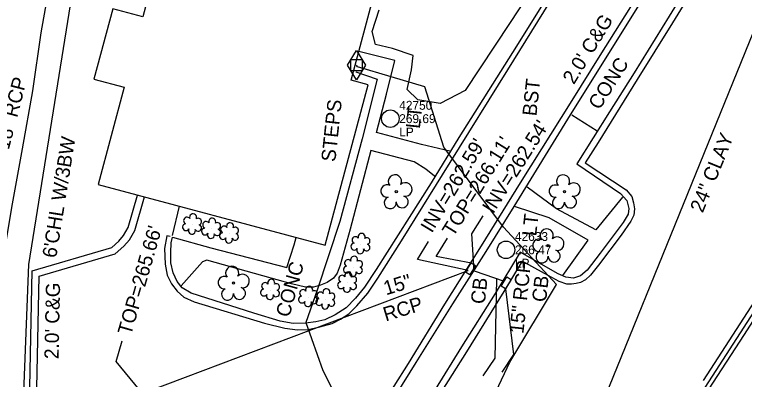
# Model space of a CAD drawing. Extents: x 2100323 to 2109811, y 740376 to 749755.
# Drawn here: x 2105531.2 to 2105736.4, y 742326 to 742428.5 of the extents above; entities that cross this region are included whole.
import ezdxf

# ---------------------------------------------------------------- set-up
doc = ezdxf.new("R2010")
doc.units = 0
for name, color, linetype in [('Exist Building', 7, 'Continuous'), ('Exist Other Culture Area Outline', 7, 'Continuous'), ('Exist Other Culture Area Outline Text', 7, 'Continuous'), ('Exist Other Culture Fence Line', 7, 'Continuous'), ('Exist Other Culture Fence Line Text', 7, 'Continuous'), ('Exist Roads Curbs', 7, 'Continuous'), ('Exist Roads Curbs Text', 7, 'Continuous'), ('Exist Roads EOP Other', 7, 'Continuous'), ('Exist Roads EOP Other Text', 7, 'Continuous'), ('Exist Structure Minor Catch Basin', 7, 'Continuous'), ('Exist Structure Minor Catch Basin Text', 7, 'Continuous'), ('Exist Structure Minor Catch Basin Top Elevation', 7, 'Continuous'), ('Exist Structure Minor Drop Inlet Top Elevation', 7, 'Continuous'), ('Exist Structure Minor Pipes RCP 15 Inch', 7, 'Continuous'), ('Exist Structure Minor Pipes RCP 15 Inch Invert', 7, 'Continuous'), ('Exist Structure Minor Pipes RCP 15 Inch Leader', 7, 'Continuous'), ('Exist Structure Minor Pipes RCP 15 Inch Text', 7, 'Continuous'), ('Exist Structure Minor Pipes RCP 18 Inch Invert', 7, 'Continuous'), ('Exist Utilities Gas Meter CELL', 7, 'Continuous'), ('Exist Utilities Gas UG Line SUE LOS B', 7, 'Continuous'), ('Exist Utilities Other Pole CELL', 7, 'Continuous'), ('Exist Utilities Other Pole Cogo Comment', 7, 'Continuous'), ('Exist Utilities Other Pole Cogo Elevation', 7, 'Continuous'), ('Exist Utilities Other Pole Cogo Number', 7, 'Continuous'), ('Exist Utilities Other Pole Text', 7, 'Continuous'), ('Exist Utilities Power UG Cable SUE LOS B', 7, 'Continuous'), ('Exist Utilities Sanitary Sewer UG Line', 7, 'Continuous'), ('Exist Utilities Sanitary Sewer UG Line Text', 7, 'Continuous'), ('Exist Vegetation Shrub CELL', 7, 'Continuous'), ('Exist Vegetation Tree CELL', 7, 'Continuous'), ('Exist Vegetation Woods Line', 7, 'Continuous')]:
    doc.layers.add(name, color=color, linetype=linetype)

msp = doc.modelspace()

# ---------------------------------------------------------------- linework, layer by layer
at = {"layer": 'Exist Building'}
msp.add_lwpolyline([(2105596.14, 742536.08), (2105567.25, 742427.88), (2105558.83, 742430.13), (2105553.55, 742410.38), (2105562.04, 742408.11), (2105554.73, 742380.72), (2105618.6, 742363.67), (2105630.65, 742408.77), (2105625.88, 742410.05), (2105632.74, 742435.75), (2105644.12, 742432.72), (2105651.94, 742461.99), (2105640.03, 742465.17), (2105654.78, 742520.42)], close=True, dxfattribs=at)
for points in [[(2105670.98, 742240.15), (2105682.89, 742258.66), (2105692.8, 742273.74), (2105709.7, 742299.48), (2105723.54, 742320.83), (2105738.21, 742343.59), (2105757.16, 742372.53), (2105770.97, 742393.51), (2105781.47, 742409.84), (2105802.03, 742441.27), (2105818.56, 742466.6)], [(2105575.65, 742366.38), (2105577.59, 742374.62)]]:
    msp.add_lwpolyline(points, dxfattribs=at)
at = {"layer": 'Exist Other Culture Area Outline'}
for points in [[(2105653.58, 742390.07), (2105645.68, 742391.97), (2105633.01, 742395.33), (2105635.8, 742406.1), (2105638.1, 742415.58), (2105628.05, 742418.17)], [(2105695, 742395.73), (2105687.91, 742400.26)], [(2105649.32, 742383.1), (2105646.89, 742385.09), (2105643.56, 742387.13), (2105631.38, 742390.32), (2105625.57, 742368.2), (2105622.81, 742358.04), (2105621.96, 742355.8), (2105620.94, 742354.4), (2105619.12, 742353.17), (2105617.25, 742352.42), (2105615.32, 742351.93), (2105612.98, 742351.89), (2105609.12, 742352.82), (2105600.99, 742355.1), (2105585.27, 742359.5), (2105584.08, 742359.04), (2105578.1, 742352.28)], [(2105702.12, 742377.16), (2105694.64, 742367.97), (2105683.57, 742373.95), (2105675.31, 742379.99)], [(2105685.36, 742355.15), (2105692.46, 742365.1), (2105681.58, 742371.38), (2105671.8, 742374.52)], [(2105575.64, 742365.95), (2105586.38, 742362.98), (2105607.78, 742357.43), (2105609.87, 742363.75), (2105610.36, 742365.87)]]:
    msp.add_lwpolyline(points, dxfattribs=at)
at = {"layer": 'Exist Other Culture Fence Line'}
for points in [[(2105532.84, 742296.01), (2105535.28, 742358.25), (2105552.31, 742464.54)], [(2105598.74, 742236.53), (2105628.53, 742225.99), (2105656.39, 742215.68), (2105671.05, 742239.06), (2105693.86, 742273.76), (2105715.01, 742305.6), (2105736.43, 742338.64), (2105757.27, 742371), (2105783.06, 742409.27), (2105785.25, 742412.99), (2105810.8, 742452.1), (2105819.72, 742465.67)]]:
    msp.add_lwpolyline(points, dxfattribs=at)
at = {"layer": 'Exist Roads Curbs'}
for points in [[(2105690.33, 742448.48), (2105671.22, 742417.88), (2105656.15, 742393.95), (2105648.36, 742381.17), (2105632.9, 742356.84), (2105629.65, 742351.91), (2105627.09, 742348.77), (2105624.42, 742346.09), (2105621.36, 742344.13), (2105618.47, 742342.74), (2105615.94, 742342.14), (2105612.99, 742341.76), (2105609.57, 742341.66), (2105605.93, 742342.36), (2105598.49, 742344.58), (2105580.85, 742350.19), (2105578.34, 742351.75), (2105576.98, 742353.5), (2105575.81, 742355.91), (2105575.19, 742358.71), (2105575.18, 742361.62), (2105575.28, 742364.34), (2105575.64, 742365.95)], [(2105725.62, 742444.93), (2105715.29, 742428.05), (2105705.47, 742412.16), (2105698.53, 742401.2), (2105689.34, 742386.6), (2105701.64, 742378.23), (2105703.35, 742376.24), (2105703.98, 742373.97), (2105703.77, 742372.45), (2105702.38, 742370.1), (2105695.89, 742361.46), (2105692.2, 742356.71), (2105690.33, 742355.05), (2105688.34, 742354.41), (2105686.26, 742354.72), (2105684.05, 742355.65), (2105673.41, 742361.75), (2105666.4, 742350.11), (2105656.91, 742335.11), (2105649.49, 742323.1)], [(2105631.35, 742310.24), (2105644.11, 742330.75), (2105654.42, 742347.24), (2105663.84, 742361.96), (2105671.7, 742374.58), (2105687.56, 742400.31), (2105696.19, 742414.13), (2105707.73, 742432.51)], [(2105535.38, 742319.12), (2105536.16, 742356.48), (2105558.53, 742363.03), (2105560.54, 742364.83), (2105561.86, 742366.4), (2105563.19, 742368.62), (2105565.81, 742377.76)]]:
    msp.add_lwpolyline(points, dxfattribs=at)
at = {"layer": 'Exist Roads EOP Other'}
for points in [[(2105574.95, 742366.16), (2105574, 742366.32), (2105573.39, 742362.75), (2105573.6, 742358.39), (2105574.17, 742355.24), (2105575.35, 742352.81), (2105576.95, 742350.79), (2105578.79, 742349.12), (2105581.72, 742347.78), (2105601.53, 742341.78), (2105607.17, 742340.41), (2105610.81, 742339.89), (2105613.82, 742340.03), (2105617.09, 742340.71), (2105620.54, 742341.69), (2105622.87, 742342.91), (2105625.22, 742344.38), (2105627.44, 742346.64), (2105630.52, 742350.18), (2105633.33, 742354.4), (2105640.04, 742364.91), (2105653.7, 742386.93), (2105669.91, 742412.94), (2105691.35, 742447.65)], [(2105727.17, 742444.03), (2105716.19, 742426.18), (2105706.26, 742410.28), (2105695.31, 742392.56), (2105691.64, 742386.88), (2105703.19, 742379.23), (2105704.75, 742377.38), (2105705.24, 742375.63), (2105705.51, 742373.89), (2105705.3, 742372.13), (2105704.51, 742370.44), (2105701.82, 742366.47), (2105695.45, 742358.05), (2105693.17, 742355.27), (2105691.73, 742353.99), (2105690.34, 742353.21), (2105689.09, 742352.96), (2105687.82, 742352.77), (2105686.52, 742352.75), (2105684.38, 742353.52), (2105680.21, 742355.76), (2105673.92, 742359.23), (2105668.82, 742350.69), (2105658.26, 742333.74), (2105651.37, 742322.75)], [(2105629.87, 742311.31), (2105641.97, 742330.45), (2105652.16, 742347.14), (2105662.55, 742363.47), (2105673.5, 742381.18), (2105687.98, 742404.35), (2105695.91, 742417.01), (2105704.48, 742430.65)], [(2105537.38, 742319.08), (2105538.13, 742354.97), (2105559.53, 742361.24), (2105561.97, 742363.43), (2105563.5, 742365.23), (2105565.04, 742367.82), (2105567.74, 742377.25)], [(2105724.97, 742325.62), (2105741.46, 742351.13)]]:
    msp.add_lwpolyline(points, dxfattribs=at)
at = {"layer": 'Exist Structure Minor Catch Basin'}
for points in [[(2105660.85, 742357.95), (2105659.2, 742355.33), (2105657.97, 742356.1), (2105659.62, 742358.72)], [(2105668.04, 742352.18), (2105669.62, 742354.78), (2105670.87, 742354.02), (2105669.28, 742351.42)]]:
    msp.add_lwpolyline(points, close=True, dxfattribs=at)
at = {"layer": 'Exist Structure Minor Catch Basin Top Elevation'}
for points in [[(2105659.66, 742358.68), (2105649.81, 742360.52), (2105652.98, 742365.62)], [(2105669.25, 742351.39), (2105671.52, 742332.99), (2105668.19, 742328)]]:
    msp.add_lwpolyline(points, dxfattribs=at)
at = {"layer": 'Exist Structure Minor Drop Inlet Top Elevation'}
msp.add_lwpolyline([(2105567.67, 742321.49), (2105559.82, 742331.04), (2105561.49, 742336.81)], dxfattribs=at)
at = {"layer": 'Exist Structure Minor Pipes RCP 15 Inch'}
for p, q in [((2105569.35, 742322.87), (2105658.72, 742356.6)), ((2105660.46, 742356.51), (2105668.88, 742353.6))]:
    msp.add_line(p, q, dxfattribs=at)
at = {"layer": 'Exist Structure Minor Pipes RCP 15 Inch Leader'}
for points in [[(2105660.46, 742356.51), (2105659.79, 742366.9), (2105663.01, 742371.95)], [(2105658.72, 742356.6), (2105644.51, 742359.64), (2105647.62, 742364.77)], [(2105666.77, 742354.12), (2105666.25, 742331.95), (2105662.9, 742326.97)]]:
    msp.add_lwpolyline(points, dxfattribs=at)
at = {"layer": 'Exist Utilities Gas Meter CELL'}
msp.add_line((2105627.35, 742414.31), (2105627.35, 742414.31), dxfattribs=at)
for points in [[(2105624.81, 742414.31), (2105627.35, 742418.42), (2105629.88, 742414.31), (2105627.35, 742410.2), (2105624.81, 742414.31)], [(2105625.77, 742415.85), (2105628.92, 742415.85), (2105628.92, 742412.73), (2105625.77, 742412.73), (2105625.77, 742415.85)]]:
    msp.add_lwpolyline(points, dxfattribs=at)
at = {"layer": 'Exist Utilities Gas UG Line SUE LOS B'}
msp.add_line((2105627.68, 742413.82), (2105627.35, 742414.31), dxfattribs=at)
msp.add_lwpolyline([(2105621.87, 742196.44), (2105629.21, 742222.43), (2105640.07, 742255.06), (2105652.79, 742293.27), (2105670.44, 742330.82), (2105683.57, 742352.64), (2105668.7, 742368.71), (2105651.94, 742391.28), (2105646.56, 742408.24), (2105627.68, 742413.82)], dxfattribs=at)
at = {"layer": 'Exist Utilities Other Pole CELL'}
for centre in [(2105636.88, 742399.25), (2105669.42, 742362.39)]:
    msp.add_circle(centre, 2.46, dxfattribs=at)
at = {"layer": 'Exist Utilities Power UG Cable SUE LOS B'}
msp.add_lwpolyline([(2105627.18, 742412.38), (2105633.14, 742410.35), (2105628.96, 742393.54), (2105622.65, 742370.31), (2105616.29, 742351.02), (2105613.16, 742341.94), (2105617.86, 742328.48), (2105629.06, 742306.45), (2105642.48, 742279.45), (2105655.27, 742257.66), (2105667.79, 742236.89), (2105675, 742225.27), (2105677.28, 742216.75), (2105678.59, 742214.29)], dxfattribs=at)
at = {"layer": 'Exist Utilities Sanitary Sewer UG Line'}
msp.add_line((2105647.5, 742198.64), (2105754.97, 742463.04), dxfattribs=at)
at = {"layer": 'Exist Vegetation Shrub CELL'}
for p, q in [((2105581.21, 742369.47), (2105581.21, 742369.47)), ((2105586.57, 742368.25), (2105586.57, 742368.25)), ((2105591.6, 742366.95), (2105591.6, 742366.95)), ((2105628.56, 742363.98), (2105628.56, 742363.98)), ((2105626.46, 742357.55), (2105626.46, 742357.55)), ((2105624.81, 742353.13), (2105624.81, 742353.13)), ((2105603.15, 742351.08), (2105603.15, 742351.08)), ((2105613.83, 742349.11), (2105613.83, 742349.11)), ((2105618.68, 742348.41), (2105618.68, 742348.41))]:
    msp.add_line(p, q, dxfattribs=at)
for centre, radius, start, end in [((2105581.44, 742371.51), 0.99, 334.8391, 200.4717), ((2105579.72, 742370.59), 0.968, 35.8908, 245.4216), ((2105582.88, 742370.33), 0.929, 284.4567, 126.0861), ((2105585.09, 742369.38), 0.968, 35.8908, 245.4216), ((2105586.8, 742370.29), 0.99, 334.8391, 200.4717), ((2105588.24, 742369.12), 0.929, 284.4567, 126.0861), ((2105579.41, 742368.76), 0.955, 95.1099, 327.9534), ((2105581.08, 742367.78), 0.984, 151.2797, 21.387), ((2105582.84, 742368.54), 0.937, 204.9913, 73.4601), ((2105584.77, 742367.54), 0.955, 95.1099, 327.9534), ((2105588.21, 742367.32), 0.937, 204.9913, 73.4601), ((2105590.12, 742368.08), 0.968, 35.8908, 245.4216), ((2105591.83, 742368.99), 0.99, 334.8391, 200.4717), ((2105593.27, 742367.82), 0.929, 284.4567, 126.0861), ((2105586.44, 742366.57), 0.984, 151.2797, 21.387), ((2105589.8, 742366.25), 0.955, 95.1099, 327.9534), ((2105593.24, 742366.02), 0.937, 204.9913, 73.4601), ((2105627.08, 742365.1), 0.968, 35.8908, 245.4216), ((2105628.79, 742366.02), 0.99, 334.8391, 200.4717), ((2105591.47, 742365.27), 0.984, 151.2797, 21.387), ((2105626.76, 742363.27), 0.955, 95.1099, 327.9534), ((2105630.2, 742363.05), 0.937, 204.9913, 73.4601), ((2105630.23, 742364.85), 0.929, 284.4567, 126.0861), ((2105628.43, 742362.29), 0.984, 151.2797, 21.387), ((2105626.69, 742359.59), 0.99, 334.8391, 200.4717), ((2105624.66, 742356.84), 0.955, 95.1099, 327.9534), ((2105624.98, 742358.67), 0.968, 35.8908, 245.4216), ((2105628.14, 742358.41), 0.929, 284.4567, 126.0861), ((2105625.04, 742355.17), 0.99, 334.8391, 200.4717), ((2105626.33, 742355.86), 0.984, 151.2797, 21.387), ((2105628.1, 742356.62), 0.937, 204.9913, 73.4601), ((2105603.38, 742353.12), 0.99, 334.8391, 200.4717), ((2105623.33, 742354.26), 0.968, 35.8908, 245.4216), ((2105626.48, 742354), 0.929, 284.4567, 126.0861), ((2105601.66, 742352.2), 0.968, 35.8908, 245.4216), ((2105604.82, 742351.95), 0.929, 284.4567, 126.0861), ((2105614.06, 742351.15), 0.99, 334.8391, 200.4717), ((2105623.01, 742352.43), 0.955, 95.1099, 327.9534), ((2105624.68, 742351.45), 0.984, 151.2797, 21.387), ((2105626.45, 742352.2), 0.937, 204.9913, 73.4601), ((2105601.35, 742350.37), 0.955, 95.1099, 327.9534), ((2105603.02, 742349.39), 0.984, 151.2797, 21.387), ((2105604.78, 742350.15), 0.937, 204.9913, 73.4601), ((2105612.35, 742350.24), 0.968, 35.8908, 245.4216), ((2105615.5, 742349.98), 0.929, 284.4567, 126.0861), ((2105617.2, 742349.54), 0.968, 35.8908, 245.4216), ((2105618.91, 742350.45), 0.99, 334.8391, 200.4717), ((2105620.35, 742349.28), 0.929, 284.4567, 126.0861), ((2105612.03, 742348.41), 0.955, 95.1099, 327.9534), ((2105613.7, 742347.43), 0.984, 151.2797, 21.387), ((2105615.47, 742348.18), 0.937, 204.9913, 73.4601), ((2105616.88, 742347.7), 0.955, 95.1099, 327.9534), ((2105620.32, 742347.48), 0.937, 204.9913, 73.4601), ((2105618.55, 742346.72), 0.984, 151.2797, 21.387)]:
    msp.add_arc(centre, radius, start, end, dxfattribs=at)
at = {"layer": 'Exist Vegetation Tree CELL'}
for p, q in [((2105638.55, 742378.76), (2105638.55, 742378.76)), ((2105685.85, 742378.74), (2105685.85, 742378.74)), ((2105681.25, 742363.52), (2105681.25, 742363.52)), ((2105592.78, 742353.03), (2105592.78, 742353.03))]:
    msp.add_line(p, q, dxfattribs=at)
for centre in [(2105638.55, 742378.76), (2105685.85, 742378.74), (2105681.25, 742363.52), (2105592.78, 742353.03)]:
    msp.add_circle(centre, 0.326, dxfattribs=at)
for centre, radius, start, end in [((2105638.17, 742381.64), 1.86, 330.1651, 219.7134), ((2105685.46, 742381.61), 1.86, 330.1651, 219.7134), ((2105635.95, 742378.92), 1.73, 62.6636, 279.3457), ((2105641.1, 742379.35), 1.9, 257.1011, 134.1999), ((2105683.24, 742378.89), 1.73, 62.6636, 279.3457), ((2105688.4, 742379.33), 1.9, 257.1011, 134.1999), ((2105636.85, 742375.64), 1.69, 111.5671, 6.231), ((2105640.22, 742375.87), 1.7, 181.2822, 74.56), ((2105684.14, 742375.62), 1.69, 111.5671, 6.231), ((2105687.52, 742375.84), 1.7, 181.2822, 74.56), ((2105680.86, 742366.39), 1.86, 330.1651, 219.7134), ((2105683.8, 742364.11), 1.9, 257.1011, 134.1999), ((2105678.64, 742363.67), 1.73, 62.6636, 279.3457), ((2105679.54, 742360.4), 1.69, 111.5671, 6.231), ((2105682.92, 742360.62), 1.7, 181.2822, 74.56), ((2105592.4, 742355.9), 1.86, 330.1651, 219.7134), ((2105590.18, 742353.18), 1.73, 62.6636, 279.3457), ((2105595.33, 742353.61), 1.9, 257.1011, 134.1999), ((2105594.46, 742350.13), 1.7, 181.2822, 74.56), ((2105591.08, 742349.9), 1.69, 111.5671, 6.231)]:
    msp.add_arc(centre, radius, start, end, dxfattribs=at)
at = {"layer": 'Exist Vegetation Woods Line'}
for points in [[(2105552.79, 742508.71), (2105544.26, 742455.02), (2105538.65, 742423.41), (2105536.26, 742407.05), (2105533.35, 742390.8), (2105530.38, 742374.26), (2105527.72, 742358.43), (2105524.79, 742343.82), (2105522.54, 742318.78), (2105523.09, 742308.53), (2105522.51, 742299.08), (2105522.36, 742292.95), (2105522.18, 742288.01)], [(2105691.59, 742458.19), (2105670.42, 742425.97), (2105657.94, 742407.15), (2105650.92, 742403.52), (2105644.65, 742404.56), (2105641.58, 742407.46), (2105642.83, 742412.99), (2105643.34, 742417.02), (2105637.49, 742419), (2105632.75, 742420.08), (2105631.75, 742423.78), (2105633.71, 742429.87)]]:
    msp.add_lwpolyline(points, dxfattribs=at)

# ---------------------------------------------------------------- texts
at = {"layer": 'Exist Other Culture Area Outline Text'}
for s, rotation, p in [('STEPS', 83.8864, (2105621.4, 742386.98)), ('CONC', 74.5737, (2105608.45, 742343.2))]:
    msp.add_text(s, height=4, rotation=rotation, dxfattribs=at).set_placement(p)
at = {"layer": 'Exist Other Culture Fence Line Text'}
msp.add_text("6'CHL W/3BW", height=4, rotation=80.8953, dxfattribs=at).set_placement((2105542.93, 742359.95))
at = {"layer": 'Exist Roads Curbs Text'}
msp.add_text('CONC', height=4, rotation=57.6633, dxfattribs=at).set_placement((2105695.65, 742401.48))
at = {"layer": 'Exist Roads EOP Other Text'}
for s, rotation, p in [("2.0' C&G", 58.5967, (2105688.47, 742408.64)), ('BST', 83.9168, (2105677.95, 742399.85)), ("2.0' C&G", 88.8296, (2105543.6, 742331.65))]:
    msp.add_text(s, height=4, rotation=rotation, dxfattribs=at).set_placement(p)
at = {"layer": 'Exist Structure Minor Catch Basin Text'}
for p in [(2105663.44, 742347.01), (2105680.66, 742347.57)]:
    msp.add_text('CB', height=4, rotation=83.8864, dxfattribs=at).set_placement(p)
at = {"layer": 'Exist Structure Minor Catch Basin Top Elevation'}
msp.add_text("TOP=266.11'", height=4, rotation=58.1284, dxfattribs=at).set_placement((2105654.58, 742365.82))
at = {"layer": 'Exist Structure Minor Drop Inlet Top Elevation'}
msp.add_text("TOP=265.66'", height=4, rotation=73.8326, dxfattribs=at).set_placement((2105563.96, 742338.17))
at = {"layer": 'Exist Structure Minor Pipes RCP 15 Inch Invert'}
for s, rotation, p in [("INV=262.54'", 57.4683, (2105665.79, 742372.33)), ("INV=262.59'", 58.8214, (2105648.55, 742366.9))]:
    msp.add_text(s, height=4, rotation=rotation, dxfattribs=at).set_placement(p)
at = {"layer": 'Exist Structure Minor Pipes RCP 15 Inch Text'}
for s, rotation, p in [('15" RCP', 83.8864, (2105674.28, 742338.68)), ('15"', 17.0352, (2105635.67, 742349.58)), ('RCP', 17.0352, (2105635.58, 742342.23))]:
    msp.add_text(s, height=4, rotation=rotation, dxfattribs=at).set_placement(p)
at = {"layer": 'Exist Structure Minor Pipes RCP 18 Inch Invert'}
msp.add_text('18" RCP', height=4, rotation=75.4971, dxfattribs=at).set_placement((2105529.59, 742390.34))
at = {"layer": 'Exist Utilities Other Pole Cogo Comment'}
for p in [(2105639.38, 742394.25), (2105671.92, 742357.39)]:
    msp.add_text('LP', height=2.5, dxfattribs=at).set_placement(p)
at = {"layer": 'Exist Utilities Other Pole Cogo Elevation'}
for s, p in [('269.69', (2105639.38, 742398)), ('266.47', (2105671.92, 742361.14))]:
    msp.add_text(s, height=2.5, dxfattribs=at).set_placement(p)
at = {"layer": 'Exist Utilities Other Pole Cogo Number'}
for s, p in [('42750', (2105639.38, 742401.75)), ('42633', (2105671.92, 742364.89))]:
    msp.add_text(s, height=2.5, dxfattribs=at).set_placement(p)
at = {"layer": 'Exist Utilities Other Pole Text'}
for p in [(2105645.17, 742396.3), (2105677.88, 742366.08)]:
    msp.add_text('LT', height=4, rotation=83.8864, dxfattribs=at).set_placement(p)
at = {"layer": 'Exist Utilities Sanitary Sewer UG Line Text'}
msp.add_text('24" CLAY', height=4, rotation=67.8792, dxfattribs=at).set_placement((2105724.7, 742372.57))

doc.saveas('drawing.dxf')
